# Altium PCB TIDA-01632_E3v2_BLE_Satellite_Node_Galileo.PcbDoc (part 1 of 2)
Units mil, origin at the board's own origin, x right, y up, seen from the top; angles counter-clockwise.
Board outline 3000 x 1875.2 mil, 6 copper layers (Top Layer, Layer2, Layer3, Layer4, Layer5, Bottom Layer), stack 33.151 mil thick; 76 components, 48 nets, 235 pads, 260 vias.
Unrouted connection lines stored in the file: 1.
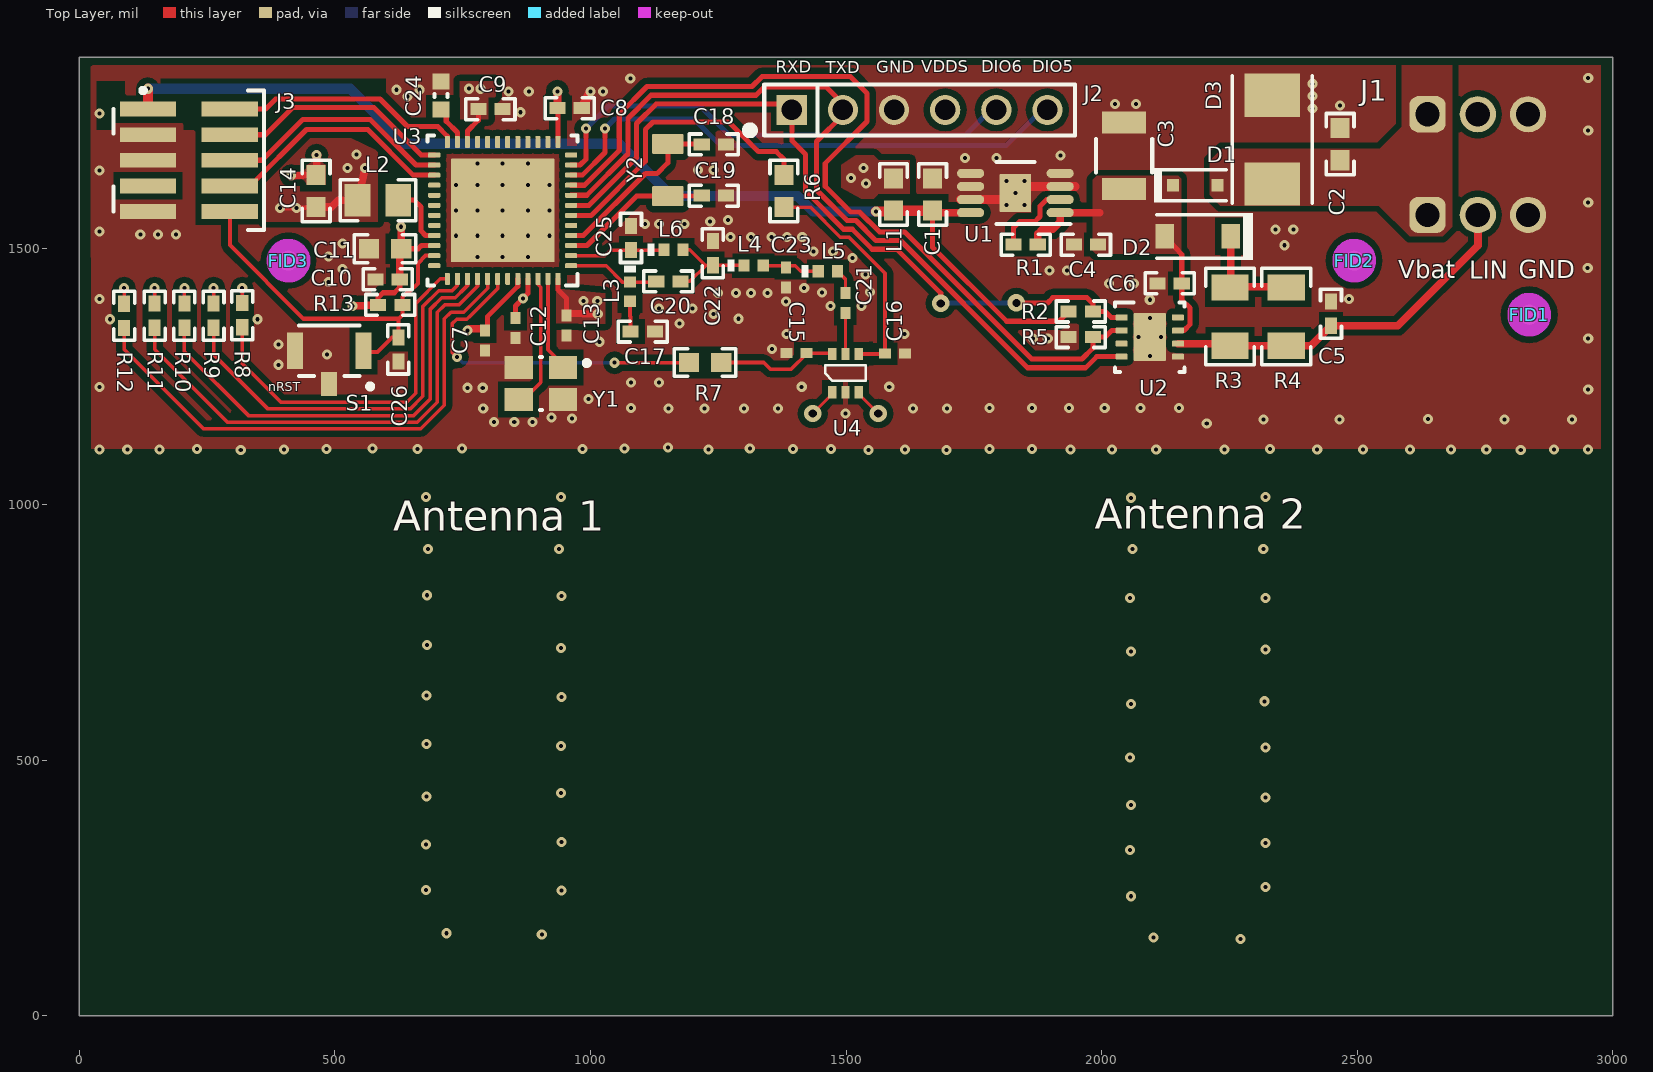
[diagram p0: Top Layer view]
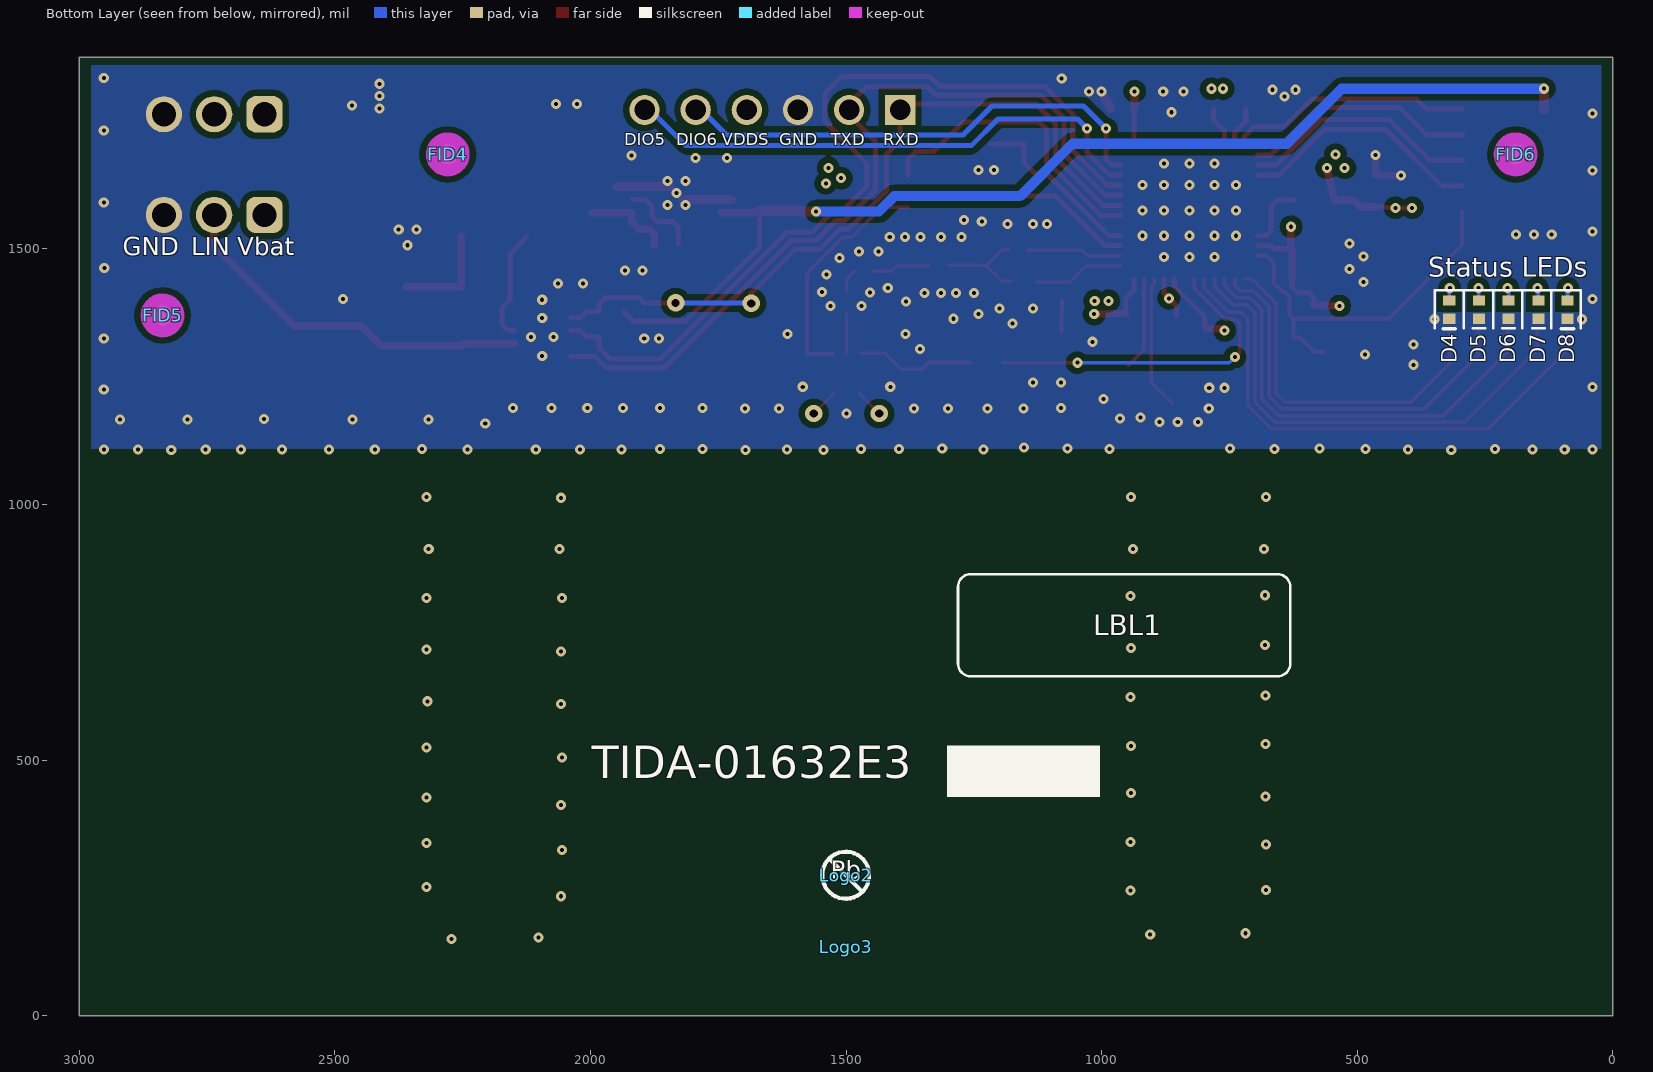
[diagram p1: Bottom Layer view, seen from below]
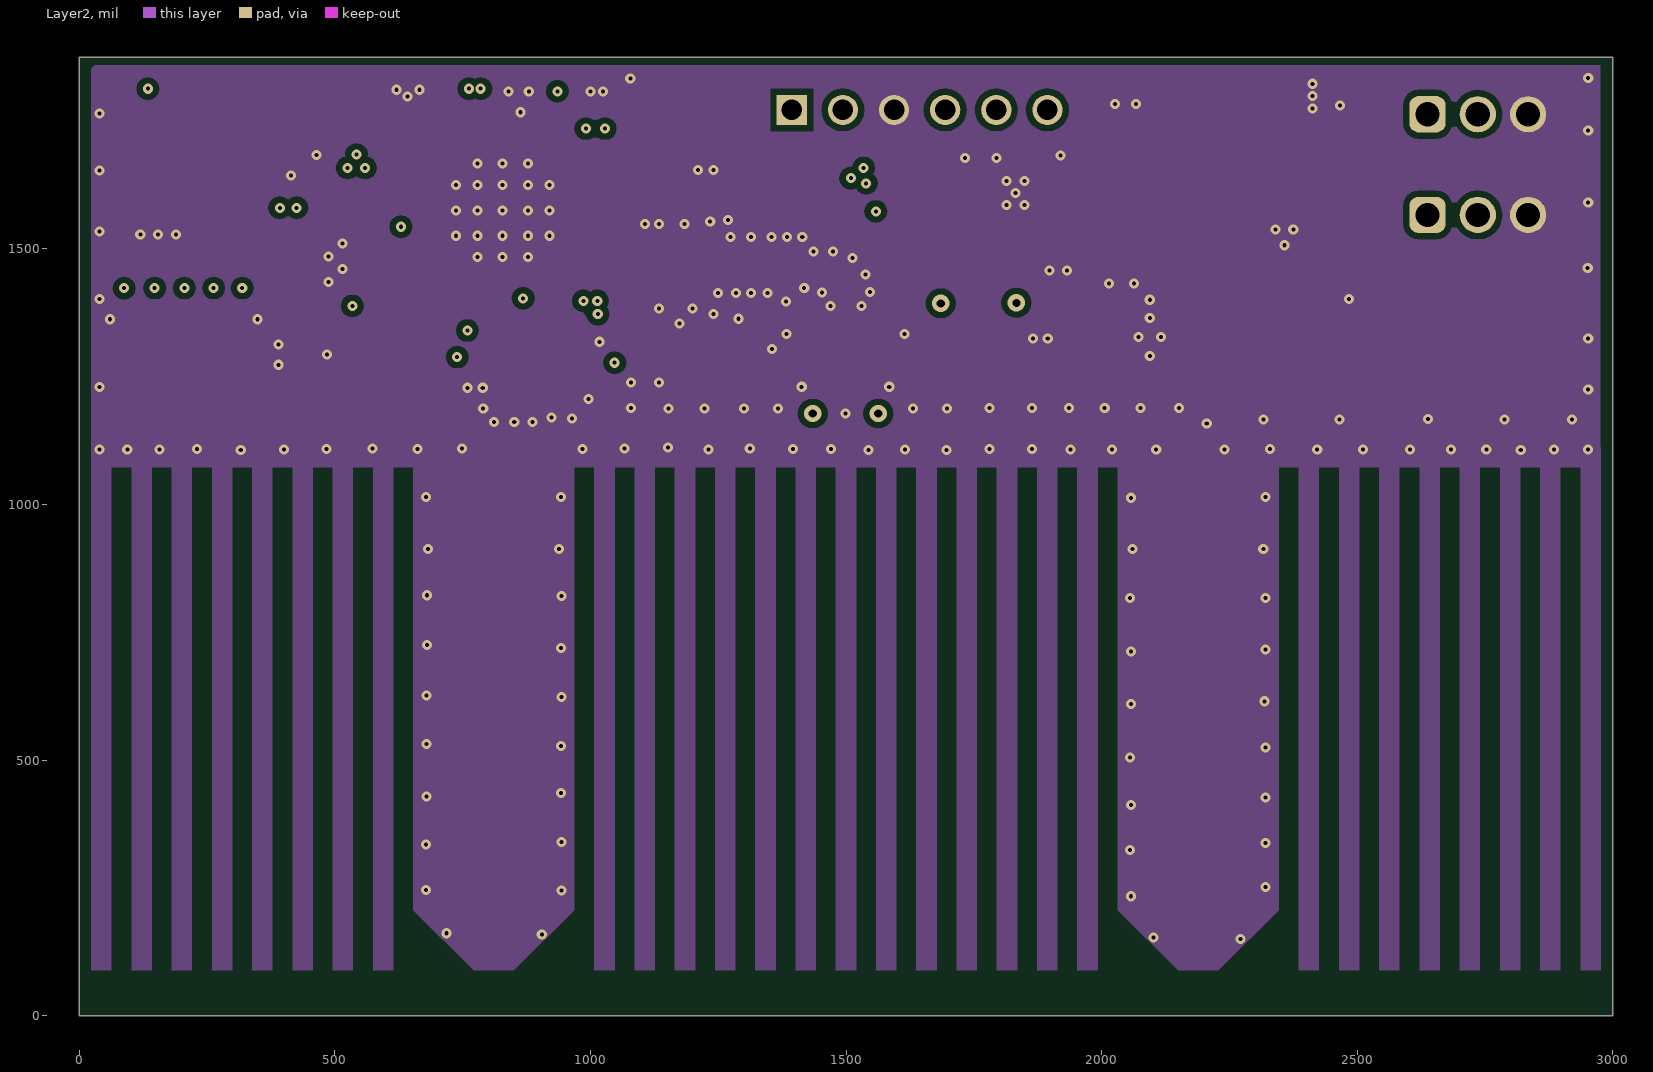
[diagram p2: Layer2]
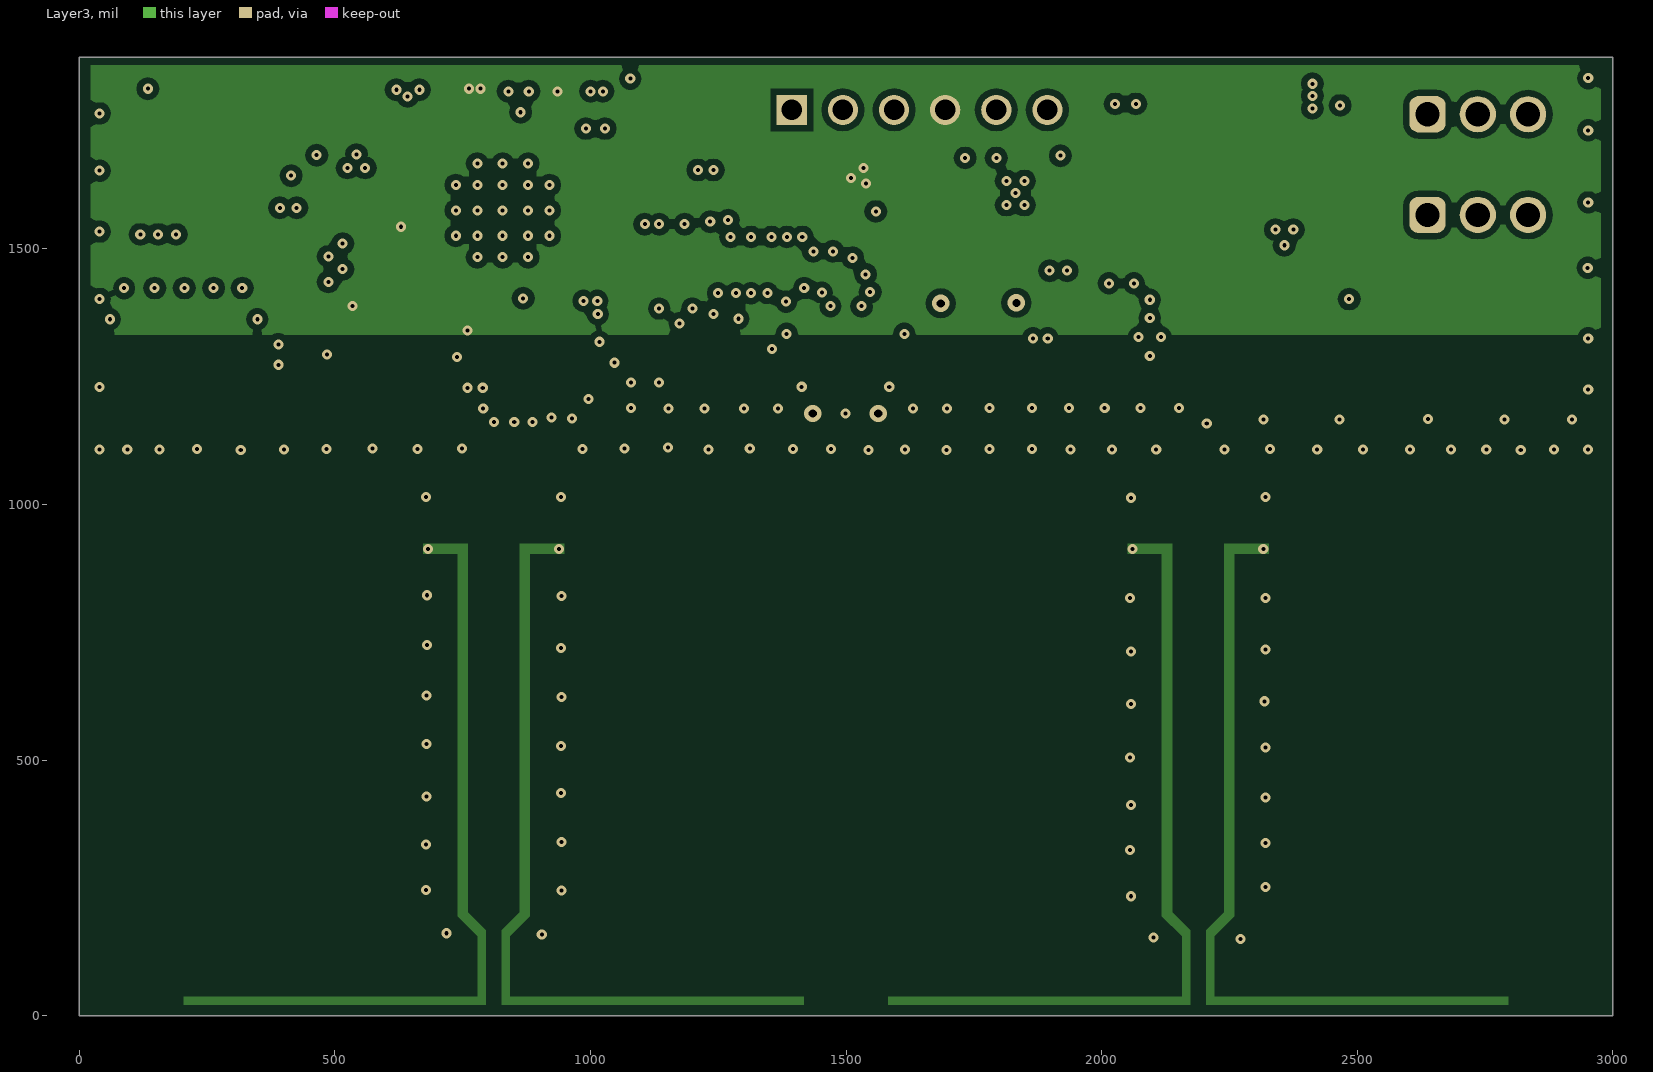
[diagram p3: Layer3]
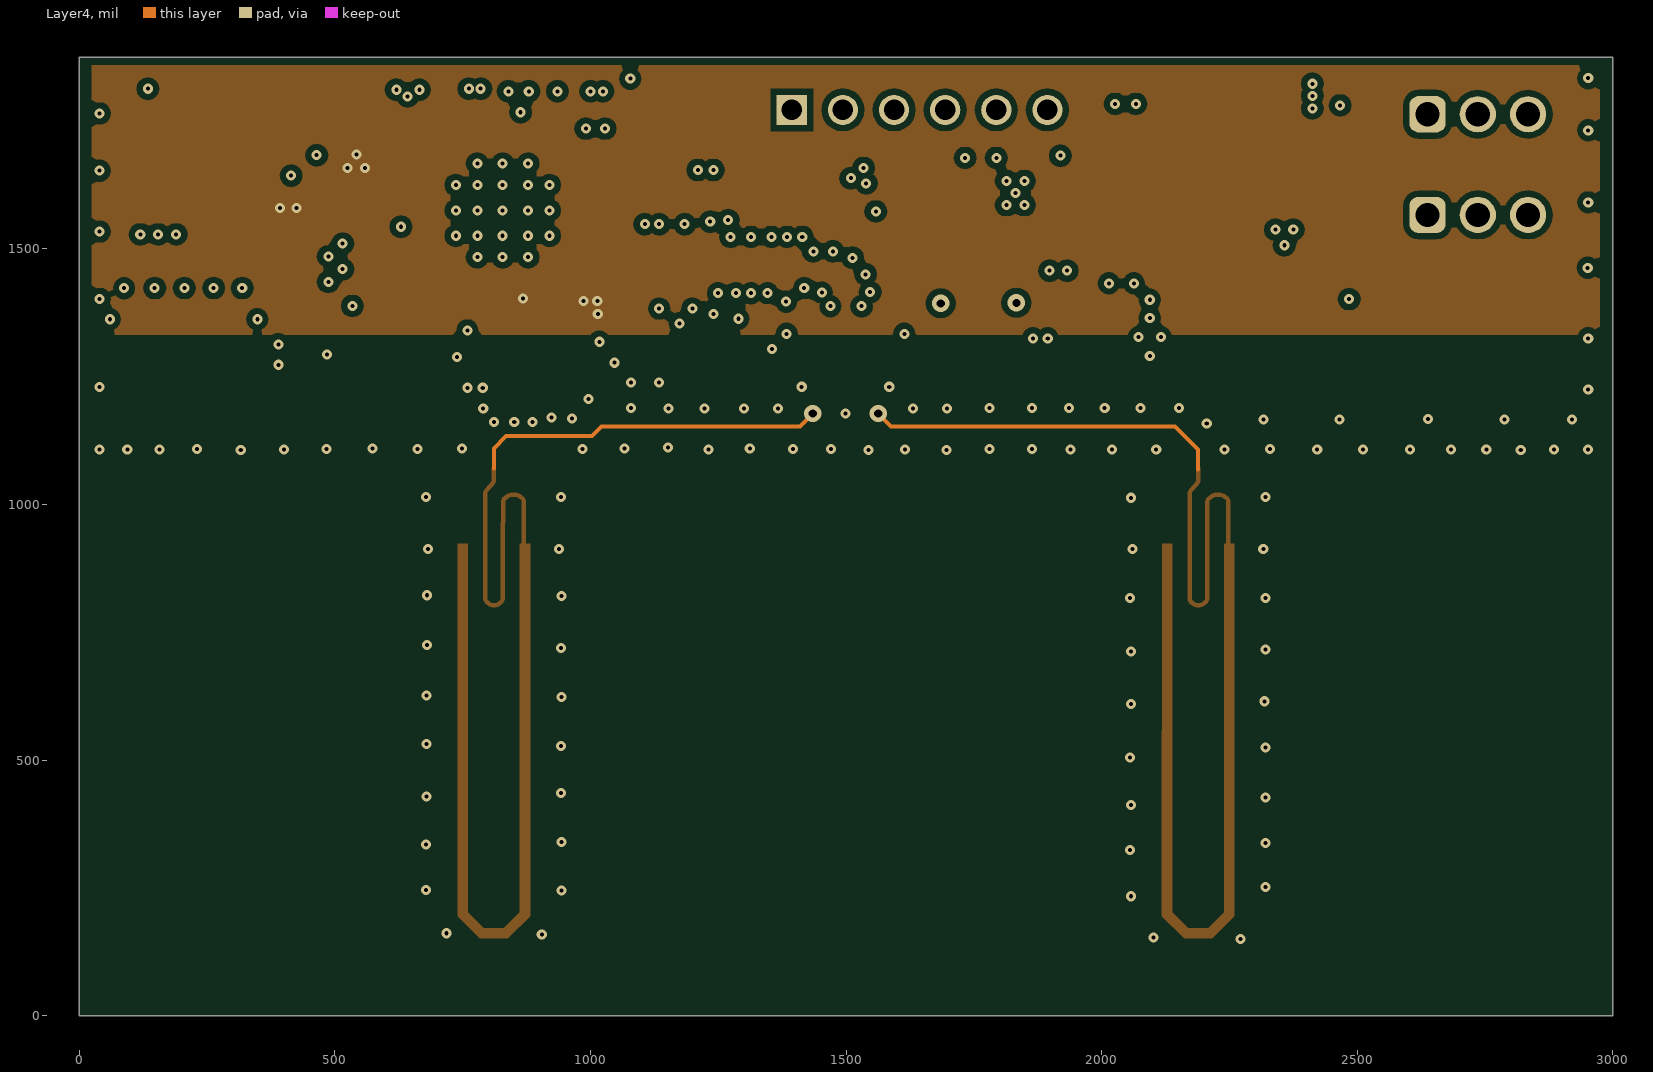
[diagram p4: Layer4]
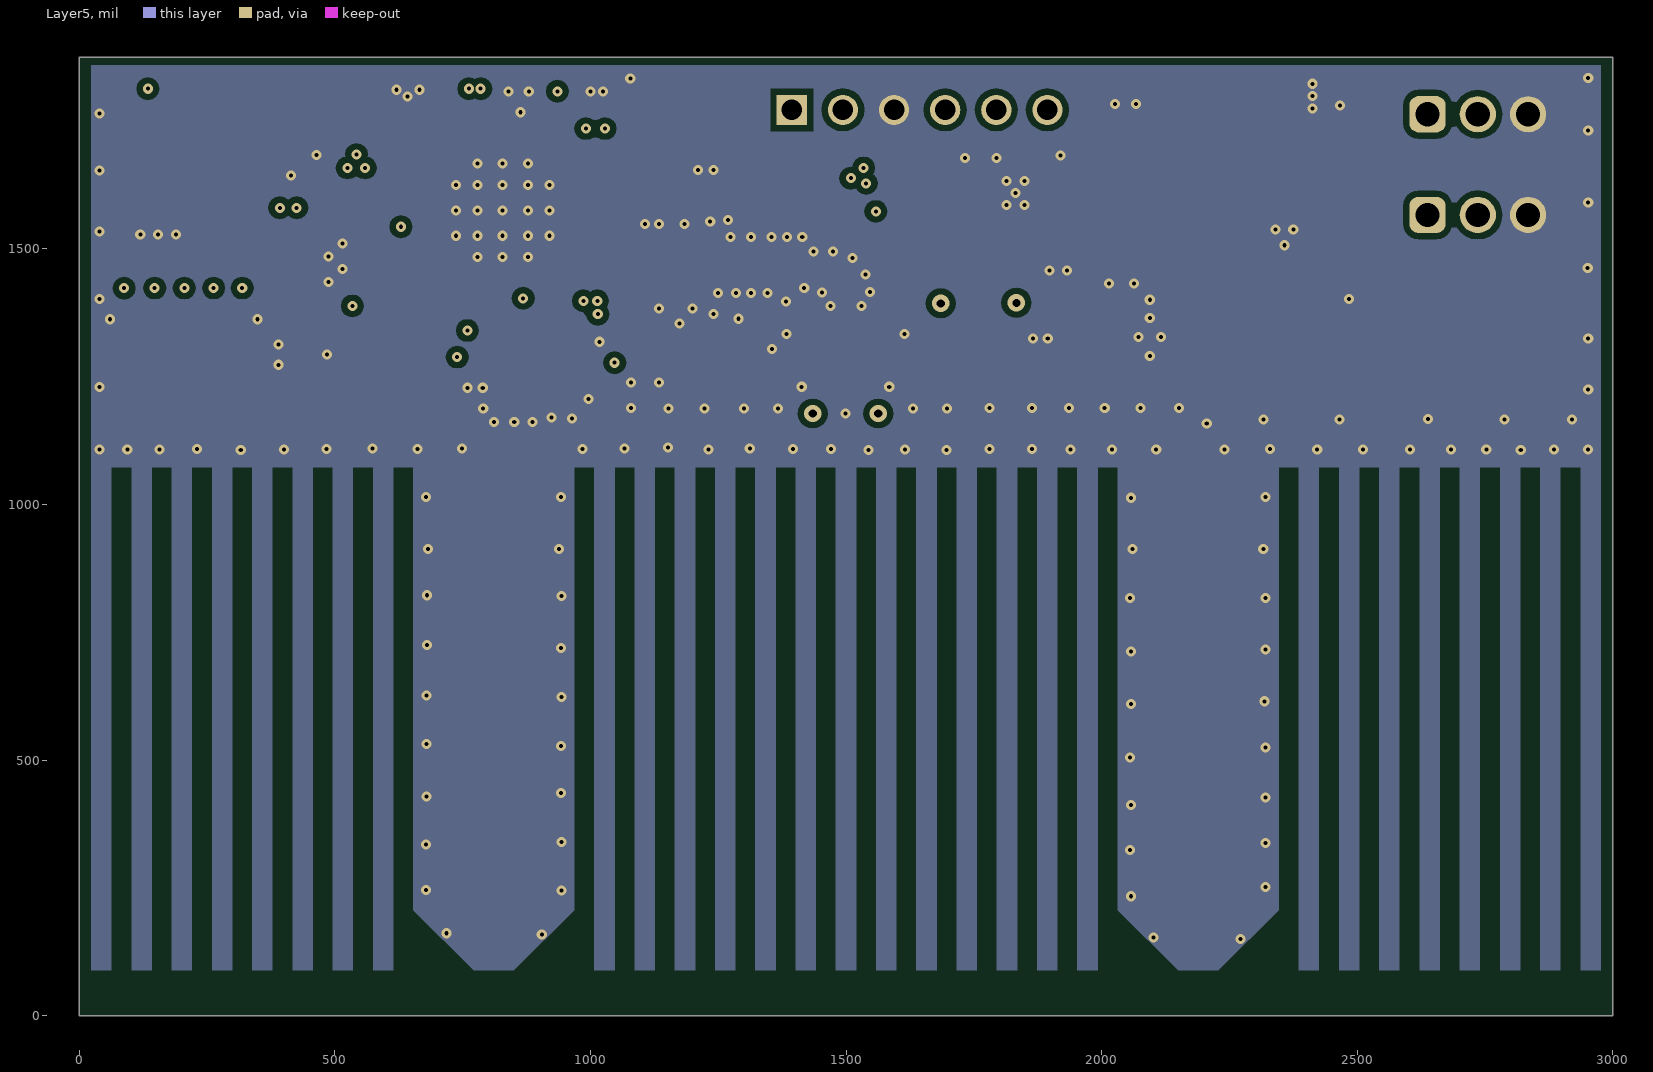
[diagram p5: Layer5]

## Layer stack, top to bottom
Top Solder: solder mask 0.4, Solder Resist, Dk 3.5
Top Layer: signal copper 1.378
Dielectric1: core 3.937, FR-4, Dk 4.1
Layer2: signal copper 0.709
Dielectric2: prepreg 7.874, FR-4, Dk 4.1
Layer3: signal copper 0.709
Dielectric3: core 3.937, FR-4, Dk 4.1
Layer4: signal copper 0.709
Dielectric4: prepreg 7.874, FR-4, Dk 4.1
Layer5: signal copper 0.709
Dielectric5: core 3.937, FR-4, Dk 4.1
Bottom Layer: signal copper 1.378
Bottom Solder: solder mask 0.4, Solder Resist, Dk 3.5

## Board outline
0,-0.2 3000,-0.2 3000,1875 0,1875

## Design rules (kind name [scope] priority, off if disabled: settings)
AcuteAngle [All] p1: minimum=4.50000000000000E+0001 checktracksonly=FALSE
AssemblyTestPointUsage [All] p1: valid=2
BoardOutlineClearance BoardOutlineClearance_MountingHoles [OnCopper and InComponentClass('Mounting Holes')] p1: gap=40 ignorepadtopadclearanceinfootprint=FALSE
BoardOutlineClearance BoardOutlineClearance_Poly [OnCopper and IsPoly] p2: gap=25 ignorepadtopadclearanceinfootprint=FALSE except(15: Poly-OutlineEdge Poly-CutoutEdge Region-OutlineEdge Region-CutoutEdge)
BoardOutlineClearance [OnCopper and Not InComponentClass('Logo') and not InComponentClass('FiducialMark') and not InRegion(1000,500,4000,800) and not InPoly] p3: gap=30 ignorepadtopadclearanceinfootprint=FALSE
Clearance Clearance_1 [InNamedPolygon('LAYER2-GND 8')] p1: gap=10 ignorepadtopadclearanceinfootprint=FALSE except(0: Arc-Hole Track-Hole SMDPad-Hole THPad-Hole Via-Hole Fill-Hole Poly-Hole Region-Hole Text-Hole)
Clearance Clearance_Keepouts [((IsTrack Or IsArc) And Not InPoly) And IsFree and IsKeepOut vs ((IsTrack Or IsArc) And Not InPoly) And IsFree and IsKeepOut] p2: gap=0 ignorepadtopadclearanceinfootprint=FALSE
Clearance Clearance_Poly [InPolygon] p3: gap=12 ignorepadtopadclearanceinfootprint=FALSE
Clearance Clearance_FiducialMark [IsKeepOut and InComponentClass('FiducialMark') vs IsPad and InComponentClass('FiducialMark')] p4: gap=0 ignorepadtopadclearanceinfootprint=FALSE
Clearance [All] p5: gap=6 ignorepadtopadclearanceinfootprint=FALSE except(0: Arc-Hole Track-Hole SMDPad-Hole THPad-Hole Via-Hole Fill-Hole Poly-Hole Region-Hole Text-Hole)
ComponentClearance ComponentClearance_MountingHoles_FiducialMarks [InComponentClass('Mounting Holes') vs InComponentClass('FiducialMark')] p1: gap=50 collisioncheckmode=3 verticalgap=10 showdistances=FALSE
ComponentClearance ComponentClearance_Shunt [InComponentClass('Header') vs InComponentClass('Shunt')] p2: gap=0 collisioncheckmode=3 verticalgap=0 showdistances=FALSE
ComponentClearance ComponentClearance_Logo [InComponentClass('Logo')] p3: gap=50 collisioncheckmode=3 verticalgap=10 showdistances=FALSE
ComponentClearance ComponentClearance_ScrewToNut [(HasFootprint('NY PMS 440 0025 PH')) vs (HasFootprint('Keystone_1902C'))] p4: gap=5 collisioncheckmode=3 verticalgap=10 showdistances=FALSE
ComponentClearance ComponentClearance_MountingHoles [InComponentClass('Mounting Holes')] p5: gap=250 collisioncheckmode=3 verticalgap=100000 showdistances=FALSE
ComponentClearance ComponentClearance_SmallPassives [HasFootprint('0201*') or HasFootprint('0402*') or HasFootprint('0508') or HasFootprint('0603*') or HasFootprint('0612') or HasFootprint('0805*') or HasFootprint('0815*') or HasFootprint('0830*') or HasFootprint('1206*') or HasFootprint('1210*') or HasFootprint('1808*') or HasFootprint('1812*') or HasFootprint('1825*') or HasFootprint('2010*') or HasFootprint('2220*') or HasFootprint('2225*') or HasFootprint('2512*') or HasFootprint('2728*') or HasFootprint('3518*') vs HasFootprint('0201*') or HasFootprint('0402*') or HasFootprint('0508') or HasFootprint('0603*') or HasFootprint('0612') or HasFootprint('0805*') or HasFootprint('0815*') or HasFootprint('0830*') or HasFootprint('1206*') or HasFootprint('1210*') or HasFootprint('1808*') or HasFootprint('1812*') or HasFootprint('1825*') or HasFootprint('2010*') or HasFootprint('2220*') or HasFootprint('2225*') or HasFootprint('2512*') or HasFootprint('2728*') or HasFootprint('3518*')] p6: gap=14.96 collisioncheckmode=3 verticalgap=10 showdistances=FALSE
ComponentClearance ComponentClearance_THtoSMT [IsThruComponent vs IsSMTComponent] p7: gap=40 collisioncheckmode=3 verticalgap=30 showdistances=FALSE
ComponentClearance ComponentClearance_THtoTH [IsThruComponent vs IsThruComponent] p8: gap=30 collisioncheckmode=3 verticalgap=30 showdistances=FALSE
ComponentClearance [All] p9: gap=30 collisioncheckmode=3 verticalgap=10 showdistances=FALSE
DiffPairsRouting [All] p1: maxlimit=100 minlimit=10 mostfreqgap=10 toplayer_minwidth=15 toplayer_maxwidth=15 toplayer_prefwidth=15 midlayer1_minwidth=15 midlayer1_maxwidth=15 midlayer1_prefwidth=15 midlayer2_minwidth=15 midlayer2_maxwidth=15 midlayer2_prefwidth=15 midlayer3_minwidth=15 midlayer3_maxwidth=15 midlayer3_prefwidth=15 midlayer4_minwidth=15 midlayer4_maxwidth=15 midlayer4_prefwidth=15 bottomlayer_minwidth=15 bottomlayer_maxwidth=15 bottomlayer_prefwidth=15 maxuncoupledlength=1000
FabricationTestPointUsage TestPointUsage [All] p1: valid=2 allowmultiple=FALSE
FabricationTestpoint Testpoint [All] p1: side=3 testpointundercomponent=TRUE minsize=40 maxsize=100 preferedsize=60 minholesize=0 maxholesize=40 preferedholesize=32 testpointgrid=1 allowsidetop=TRUE allowsidebottom=TRUE usegrid=TRUE gridtolerance=0.01
FanoutControl Fanout_LCC [IsLCC] p1: bgadir=Out bgaviamode=Centered fanoutstyle=Auto fanoutdirection=Alternating viagrid=1 // Fanout_LCC (Default Rule)
FanoutControl Fanout_BGA [IsBGA] p2: bgadir=Out bgaviamode=Centered fanoutstyle=Auto fanoutdirection=Alternating viagrid=1 // Fanout_BGA (Default Rule)
FanoutControl Fanout_Default [All] p4: bgadir=Out bgaviamode=Centered fanoutstyle=Auto fanoutdirection=Alternating viagrid=1 // Fanout_Default (Default Rule)
FanoutControl Fanout_Small [(CompPinCount < 5)] p5: bgadir=Out bgaviamode=Centered fanoutstyle=Auto fanoutdirection=OutThenIn viagrid=1 // Fanout_Small (Default Rule)
HoleSize [All] p1: absolutevalues=TRUE maxlimit=251 minlimit=7.87 maxpercent=80.000 minpercent=20.000
MinimumAnnularRing MinimumAnnularRing_ThermalPadVias [IsVia and InAnyComponent] p1: minimumring=5.9
MinimumAnnularRing [All] p2: minimumring=5.9
MinimumSolderMaskSliver MinimumSolderMaskSliver_Logo [InComponentClass('Logo') vs InComponentClass('Logo')] p1: minsoldermaskwidth=0.7
MinimumSolderMaskSliver [All] p2: minsoldermaskwidth=2.9
PlaneClearance [All] p1: clearance=15
PlaneConnect [All] p1: planeconnectstyle=Direct reliefexpansion=10 reliefentries=4 reliefconductorwidth=10 reliefairgap=10
PolygonConnect PolygonConnect_54 [All vs IsNamedPolygon('TOP_LAYER_DIO_6_P217')] p1: thpad.connectstyle=Direct thpad.reliefconductorwidth=10 thpad.reliefentries=4 thpad.polygonreliefangle="90 Angle" thpad.airgapwidth=10 smdpad.connectstyle=Direct smdpad.reliefconductorwidth=10 smdpad.reliefentries=4 smdpad.polygonreliefangle="90 Angle" smdpad.airgapwidth=10 via.connectstyle=Relief via.reliefconductorwidth=10 via.reliefentries=4 via.polygonreliefangle="90 Angle" via.airgapwidth=10
PolygonConnect PolygonConnect_53 [All vs IsNamedPolygon('TOP_LAYER_DIO_5_P216')] p2: connectstyle=Direct reliefconductorwidth=10 reliefentries=4 polygonreliefangle="90 Angle" airgapwidth=10
PolygonConnect PolygonConnect_52 [All vs IsNamedPolygon('TOP_LAYER_VDDS_P221')] p3: connectstyle=Direct reliefconductorwidth=10 reliefentries=4 polygonreliefangle="90 Angle" airgapwidth=10
PolygonConnect PolygonConnect_51 [All vs IsNamedPolygon('TOP_LAYER_VDDR_P243')] p4: connectstyle=Direct reliefconductorwidth=10 reliefentries=4 polygonreliefangle="90 Angle" airgapwidth=10
PolygonConnect PolygonConnect_50 [All vs IsNamedPolygon('TOP_LAYER_VDDR_P218')] p5: connectstyle=Direct reliefconductorwidth=10 reliefentries=4 polygonreliefangle="90 Angle" airgapwidth=10
PolygonConnect PolygonConnect_49 [All vs IsNamedPolygon('TOP_LAYER_GND_P247')] p6: connectstyle=Direct reliefconductorwidth=10 reliefentries=4 polygonreliefangle="90 Angle" airgapwidth=10
PolygonConnect PolygonConnect_48 [All vs IsNamedPolygon('TOP_LAYER_DIO_5_P247')] p7: connectstyle=Direct reliefconductorwidth=10 reliefentries=4 polygonreliefangle="90 Angle" airgapwidth=10
PolygonConnect PolygonConnect_47 [All vs IsNamedPolygon('TOP_LAYER_DIO_6_P245')] p8: connectstyle=Direct reliefconductorwidth=10 reliefentries=4 polygonreliefangle="90 Angle" airgapwidth=10
PolygonConnect PolygonConnect_46 [All vs IsNamedPolygon('TOP_LAYER_DIO_6_P245')] p9: connectstyle=Direct reliefconductorwidth=10 reliefentries=4 polygonreliefangle="90 Angle" airgapwidth=10
PolygonConnect PolygonConnect_45 [All vs IsNamedPolygon('TOP_LAYER_VDDR_P240')] p10: connectstyle=Direct reliefconductorwidth=10 reliefentries=4 polygonreliefangle="90 Angle" airgapwidth=10
PolygonConnect PolygonConnect_44 [All vs IsNamedPolygon('TOP_LAYER_VDDR_P240')] p11: connectstyle=Direct reliefconductorwidth=10 reliefentries=4 polygonreliefangle="90 Angle" airgapwidth=10
PolygonConnect PolygonConnect_43 [All vs IsNamedPolygon('TOP_LAYER_VBATT_P217')] p12: connectstyle=Direct reliefconductorwidth=10 reliefentries=4 polygonreliefangle="90 Angle" airgapwidth=10
PolygonConnect PolygonConnect_42 [All vs IsNamedPolygon('TOP_LAYER_VSUP_P218')] p13: connectstyle=Direct reliefconductorwidth=10 reliefentries=4 polygonreliefangle="90 Angle" airgapwidth=10
PolygonConnect PolygonConnect_41 [All vs IsNamedPolygon('TOP_LAYER_VDDS_P219')] p14: connectstyle=Direct reliefconductorwidth=10 reliefentries=4 polygonreliefangle="90 Angle" airgapwidth=10
PolygonConnect PolygonConnect_40 [All vs IsNamedPolygon('LAYER2_GND_P240')] p15: connectstyle=Direct reliefconductorwidth=10 reliefentries=4 polygonreliefangle="90 Angle" airgapwidth=10
PolygonConnect PolygonConnect_39 [All vs IsNamedPolygon('LAYER5_GND_P241')] p16: connectstyle=Direct reliefconductorwidth=10 reliefentries=4 polygonreliefangle="90 Angle" airgapwidth=10
PolygonConnect PolygonConnect_38 [All vs IsNamedPolygon('BOTTOM_LAYER_GND_P243')] p17: connectstyle=Direct reliefconductorwidth=10 reliefentries=4 polygonreliefangle="90 Angle" airgapwidth=10
PolygonConnect PolygonConnect_37 [All vs IsNamedPolygon('LAYER3_VDDS_P245')] p18: connectstyle=Direct reliefconductorwidth=10 reliefentries=4 polygonreliefangle="90 Angle" airgapwidth=10
PolygonConnect PolygonConnect_36 [All vs IsNamedPolygon('LAYER4_VDDR_P249')] p19: connectstyle=Direct reliefconductorwidth=10 reliefentries=4 polygonreliefangle="90 Angle" airgapwidth=10
PolygonConnect PolygonConnect_35 [All vs IsNamedPolygon('LAYER3_GND_P242')] p20: connectstyle=Direct reliefconductorwidth=10 reliefentries=4 polygonreliefangle="90 Angle" airgapwidth=10
PolygonConnect PolygonConnect_34 [All vs IsNamedPolygon('TOP_LAYER_GND_P243')] p21: connectstyle=Direct reliefconductorwidth=10 reliefentries=4 polygonreliefangle="90 Angle" airgapwidth=10
PolygonConnect PolygonConnect_33 [All vs IsNamedPolygon('LAYER4_GND_P244')] p22: connectstyle=Direct reliefconductorwidth=10 reliefentries=4 polygonreliefangle="90 Angle" airgapwidth=10
PolygonConnect PolygonConnect_32 [All vs IsNamedPolygon('TOP_LAYER_VDDR_P216')] p23: connectstyle=Direct reliefconductorwidth=10 reliefentries=4 polygonreliefangle="90 Angle" airgapwidth=10
PolygonConnect PolygonConnect_31 [All vs IsNamedPolygon('TOP_LAYER_GND_P214')] p24: connectstyle=Direct reliefconductorwidth=10 reliefentries=4 polygonreliefangle="90 Angle" airgapwidth=10
PolygonConnect PolygonConnect_30 [All vs IsNamedPolygon('TOP_LAYER_VDDR_P214')] p25: connectstyle=Direct reliefconductorwidth=10 reliefentries=4 polygonreliefangle="90 Angle" airgapwidth=10
PolygonConnect PolygonConnect_29 [All vs IsNamedPolygon('TOP_LAYER_VDDR_P208')] p26: connectstyle=Direct reliefconductorwidth=10 reliefentries=4 polygonreliefangle="90 Angle" airgapwidth=10
PolygonConnect PolygonConnect_28 [All vs IsNamedPolygon('TOP_LAYER_GND_P202')] p27: connectstyle=Direct reliefconductorwidth=10 reliefentries=4 polygonreliefangle="90 Angle" airgapwidth=10
PolygonConnect PolygonConnect_27 [All vs IsNamedPolygon('TOP_LAYER_VDDS_P142')] p28: connectstyle=Direct reliefconductorwidth=10 reliefentries=4 polygonreliefangle="90 Angle" airgapwidth=10
PolygonConnect PolygonConnect_26 [All vs IsNamedPolygon('TOP_LAYER_VSUP_P140')] p29: connectstyle=Direct reliefconductorwidth=10 reliefentries=4 polygonreliefangle="90 Angle" airgapwidth=10
PolygonConnect PolygonConnect_25 [All vs IsNamedPolygon('TOP_LAYER_VBATT_P138')] p30: connectstyle=Direct reliefconductorwidth=10 reliefentries=4 polygonreliefangle="90 Angle" airgapwidth=10
PolygonConnect PolygonConnect_24 [All vs IsNamedPolygon('TOP_LAYER_VDDS_P140')] p31: connectstyle=Direct reliefconductorwidth=10 reliefentries=4 polygonreliefangle="90 Angle" airgapwidth=10
PolygonConnect PolygonConnect_23 [All vs IsNamedPolygon('TOP_LAYER_GND_P200')] p32: connectstyle=Direct reliefconductorwidth=10 reliefentries=4 polygonreliefangle="90 Angle" airgapwidth=10
PolygonConnect PolygonConnect_22 [All vs IsNamedPolygon('TOP_LAYER_VSUP_P138')] p33: connectstyle=Direct reliefconductorwidth=10 reliefentries=4 polygonreliefangle="90 Angle" airgapwidth=10
PolygonConnect PolygonConnect_21 [All vs IsNamedPolygon('TOP_LAYER_GND_P198')] p34: connectstyle=Direct reliefconductorwidth=10 reliefentries=4 polygonreliefangle="90 Angle" airgapwidth=10
PolygonConnect PolygonConnect_20 [All vs IsNamedPolygon('TOP_LAYER_VDDS_P138')] p35: connectstyle=Direct reliefconductorwidth=10 reliefentries=4 polygonreliefangle="90 Angle" airgapwidth=10
PolygonConnect PolygonConnect_19 [All vs IsNamedPolygon('TOP_LAYER_VDDS_P202')] p36: connectstyle=Direct reliefconductorwidth=10 reliefentries=4 polygonreliefangle="90 Angle" airgapwidth=10
PolygonConnect PolygonConnect_18 [All vs IsNamedPolygon('LAYER4_VDDR_P208')] p37: connectstyle=Direct reliefconductorwidth=10 reliefentries=4 polygonreliefangle="90 Angle" airgapwidth=10
PolygonConnect PolygonConnect_17 [All vs IsNamedPolygon('LAYER3_VDDS_P206')] p38: connectstyle=Direct reliefconductorwidth=10 reliefentries=4 polygonreliefangle="90 Angle" airgapwidth=10
PolygonConnect PolygonConnect_16 [All vs IsNamedPolygon('TOP_LAYER_GND_P196')] p39: connectstyle=Direct reliefconductorwidth=10 reliefentries=4 polygonreliefangle="90 Angle" airgapwidth=10
PolygonConnect PolygonConnect_15 [All vs IsNamedPolygon('TOP_LAYER_GND_P196')] p40: connectstyle=Direct reliefconductorwidth=10 reliefentries=4 polygonreliefangle="90 Angle" airgapwidth=10
PolygonConnect PolygonConnect_14 [All vs IsNamedPolygon('BOTTOM_LAYER_GND_P202')] p41: connectstyle=Direct reliefconductorwidth=10 reliefentries=4 polygonreliefangle="90 Angle" airgapwidth=10
PolygonConnect PolygonConnect_13 [All vs IsNamedPolygon('LAYER5_GND_P200')] p42: connectstyle=Direct reliefconductorwidth=10 reliefentries=4 polygonreliefangle="90 Angle" airgapwidth=10
PolygonConnect PolygonConnect_12 [All vs IsNamedPolygon('LAYER2_GND_P198')] p43: connectstyle=Direct reliefconductorwidth=10 reliefentries=4 polygonreliefangle="90 Angle" airgapwidth=10
PolygonConnect PolygonConnect_11 [All vs IsNamedPolygon('LAYER2_GND_P198')] p44: connectstyle=Direct reliefconductorwidth=10 reliefentries=4 polygonreliefangle="90 Angle" airgapwidth=10
PolygonConnect PolygonConnect_10 [All vs IsNamedPolygon('LAYER2-GND 8')] p45: connectstyle=Direct reliefconductorwidth=10 reliefentries=4 polygonreliefangle="90 Angle" airgapwidth=10
PolygonConnect PolygonConnect_9 [All vs IsNamedPolygon('LAYER2-GND 8')] p46: connectstyle=Direct reliefconductorwidth=10 reliefentries=4 polygonreliefangle="90 Angle" airgapwidth=10
PolygonConnect PolygonConnect_8 [All vs IsNamedPolygon('LAYER5_GND_P200')] p47: thpad.connectstyle=Direct thpad.reliefconductorwidth=10 thpad.reliefentries=4 thpad.polygonreliefangle="90 Angle" thpad.airgapwidth=10 smdpad.connectstyle=NoConnect smdpad.reliefconductorwidth=10 smdpad.reliefentries=4 smdpad.polygonreliefangle="90 Angle" smdpad.airgapwidth=10 via.connectstyle=Direct via.reliefconductorwidth=10 via.reliefentries=4 via.polygonreliefangle="90 Angle" via.airgapwidth=10
PolygonConnect PolygonConnect_7 [All vs IsNamedPolygon('LAYER2_GND_P198')] p48: connectstyle=Direct reliefconductorwidth=10 reliefentries=4 polygonreliefangle="90 Angle" airgapwidth=10
PolygonConnect PolygonConnect_6 [All vs IsNamedPolygon('LAYER2-GND 8')] p49: connectstyle=Direct reliefconductorwidth=10 reliefentries=4 polygonreliefangle="90 Angle" airgapwidth=10
PolygonConnect PolygonConnect_5 [All vs IsNamedPolygon('LAYER5-GND 5') Or  IsNamedPolygon('LAYER5-GND 3') Or  IsNamedPolygon('LAYER5-GND 6') Or  IsNamedPolygon('LAYER5-GND 4') Or  IsNamedPolygon('LAYER5-GND 7') Or  IsNamedPolygon('LAYER5-GND 2')] p50: connectstyle=Direct reliefconductorwidth=10 reliefentries=4 polygonreliefangle="90 Angle" airgapwidth=10
PolygonConnect PolygonConnect_4 [All vs IsNamedPolygon('LAYER2-GND 8') Or  IsNamedPolygon('LAYER2-GND 6') Or  IsNamedPolygon('LAYER2-GND 8') Or  IsNamedPolygon('LAYER2-GND 7')] p51: connectstyle=Direct reliefconductorwidth=10 reliefentries=4 polygonreliefangle="90 Angle" airgapwidth=10
PolygonConnect PolygonConnect_3 [All vs IsNamedPolygon('LAYER3-GND 2') Or  IsNamedPolygon('LAYER3-GND 4') Or  IsNamedPolygon('LAYER3-GND 3')] p52: connectstyle=Direct reliefconductorwidth=10 reliefentries=4 polygonreliefangle="90 Angle" airgapwidth=10
PolygonConnect PolygonConnect_2 [All vs IsNamedPolygon('LAYER3-GND 5')] p53: connectstyle=Direct reliefconductorwidth=10 reliefentries=4 polygonreliefangle="90 Angle" airgapwidth=10
PolygonConnect PolygonConnect_1 [All vs IsNamedPolygon('LAYER2-GND 9') Or  IsNamedPolygon('LAYER5-GND 7')] p54: connectstyle=Direct reliefconductorwidth=10 reliefentries=4 polygonreliefangle="90 Angle" airgapwidth=10
PolygonConnect [All] p55: connectstyle=Direct reliefconductorwidth=10 reliefentries=4 polygonreliefangle="90 Angle" airgapwidth=10
RoutingVias ThermalPadVias [IsVia and InAnyComponent] p1: holewidth=7.87 width=19.68 viastyle="Through Hole" minholewidth=7.87 minwidth=19.68 maxholewidth=12.99 maxwidth=23.62
RoutingVias [All] p2: holewidth=16 width=34 viastyle="Through Hole" minholewidth=7.87 minwidth=19 maxholewidth=40 maxwidth=65
SilkToBoardRegionClearance [Not ((IsComment or IsDesignator) And (Hide <> 'False')) and not InRegion(1000,500,4000,800)] p1:
SilkToSilkClearance SilkToSilkClearance_Pb-FreeLogo [(HasFootprint('Pb-Free_Overlay_Medium') OR HasFootprint('Pb-Free_Overlay_Small')) vs (HasFootprint('Pb-Free_Overlay_Medium') OR HasFootprint('Pb-Free_Overlay_Small'))] p1: silktosilkclearance=0
SilkToSilkClearance [All] p2: silktosilkclearance=4
SilkToSolderMaskClearance SilkToComponentPadClearance [(IsPad or IsFill or IsRegion) and InAnycomponent] p1: minsilkscreentomaskgap=5 clearancetoexposedcopper=TRUE
SilkToSolderMaskClearance "Silk to Solder Mask Opening" [All] p2: minsilkscreentomaskgap=4 clearancetoexposedcopper=FALSE
SolderMaskExpansion [All] p1: expansion=1.97
UnRoutedNet [All] p1: checkbadconnections=TRUE
Width [All] p1: maxlimit=100 minlimit=5 preferedwidth=10 minimp=50.000000 maximp=50.000000 favimp=50.000000 checkconnectedcopper=TRUE
13 further rules are at their usual default settings.

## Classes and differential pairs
component class TIDA-01632_E3v2_BLE_Satellite_Node_Main_Galileo: C1 C2 C3 C4 C5 C6 C7 C8 C9 C10 C11 C12 C13 C14 C15 C16 C17 C18 C19 C20 C21 C22 C23 C24 C25 C? D1 D2 D3 D4 D5 D6 D7 D8 D? J1 J2 J3 J? L1 L2 L3 L4 L5 L6 R1 R2 R3 R4 R5 R6 R7 R8 R9 R10 R11 R12 R13 R? S1 U1 U2 U3 U4 U? Y1 Y2
component class TIDA-01632_E3v2_BLE_Satellite_Node_Hardware_Galileo: FID1 FID2 FID3 FID4 FID5 FID6 LBL1 Logo2 Logo3 ZZ1 ZZ2 ZZ3 ZZ4
component class FiducialMark: FID1 FID2 FID3 FID4 FID5 FID6
component class AssemblyNote: ZZ1 ZZ2 ZZ3 ZZ4
component class Label: LBL1
component class Header: J2

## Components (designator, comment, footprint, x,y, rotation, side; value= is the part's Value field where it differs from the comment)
C1 "GCM188R70J225KE22D" 0603 1669.41,1606.38 r90 top value=2.2uF
C2 "06035C104KAZ2A" 0603 2466.52,1704.96 r90 top value=0.1uF
C3 "UMK325AB7106KMHT" 1210_280 2044,1682 r270 top value=10uF
C4 "GCM155R71H104KE02D" 0402 1969.41,1508.51 r180 top value=0.1uF
C5 "GRM155R72A221KA01D" 0402 2448.8,1373.27 r90 top value=220pF
C6 "GCM155R71H104KE02D" 0402 2133.27,1432.59 r180 top value=0.1uF
C7 "CL05B104KP5NNNC" 0402L 794,1321 r270 top value=0.1uF
C8 "CL05B104KP5NNNC" 0402 959.41,1775.38 r0 top value=0.1uF
C9 "CL05B104KP5NNNC" 0402 804.41,1773.38 r0 top value=0.1uF
C10 "CL05B104KP5NNNC" 0402 603.41,1440.38 r180 top value=0.1uF
C11 "GRM188Z71A106MA73D" 0603 598.41,1500.38 r180 top value=10uF
C12 "CL05B104KP5NNNC" 0402L 853.41,1345.38 r270 top value=0.1uF
C13 "CL05B104KP5NNNC" 0402L 953.41,1350.38 r270 top value=0.1uF
C14 "GRM188Z71A106MA73D" 0603 463.41,1613.38 r90 top value=10uF
C15 "GRM1555C1H120JA01D" 0402L 1403,1296 r180 top value=12pF
C16 "GRM1555C1H120JA01D" 0402L 1596,1295 r0 top value=12pF
C17 "GRM1555C1H6R8CA01D" 0402 1102.41,1338.38 r0 top value=6.8pF
C18 "GRM1555C1H120JA01D" 0402 1241.41,1704.38 r0 top value=12pF
C19 "GRM1555C1H120JA01D" 0402 1241.41,1604.38 r0 top value=12pF
C20 "GRM1555C1H1R0CA01D" 0402 1152.41,1436.38 r180 top value=1pF
C21 "GRM1555C1H120JA01D" 0402L 1499,1393.94 r90 top value=12pF
C22 "GRM1555C1H1R0CA01D" 0402 1239.41,1491.62 r90 top value=1pF
C23 "GRM1555C1H1R0CA01D" 0402L 1382.41,1444.38 r270 top value=1pF
C24 "GRM188R71A105KA61D" 0603L 707.68,1799.94 r90 top value=1uF
C25 "GRM1555C1H1R0CA01D" 0402 1079.41,1521.38 r90 top value=1pF
C26 "CL05B104KP5NNNC" 0402 624.41,1303.38 r270 top value=0.1uF
D1 "BAS20HT1G" SOD-323 2183.27,1624.56 r0 top value=200V
D2 "1N4148W-TP" SOD-123 2188.27,1524.56 r180 top value=100V
D3 "SM6T39CA" SMB-Bi 2334,1714 r270 top value=39V
D4 "SML-P12PTT86" SML-P1_GREEN 319.87,1381.14 r90 bottom value=Green
D5 "SMLP12BC7TT86" LED_SMLP12_BLUE 261.8,1381.14 r270 bottom value=Blue
D6 "SML-P12YTT86" LED_SMLP12_YELLOW 203.72,1381.14 r270 bottom value=Yellow
D7 "SML-P12DTT86" LED_SMLP12_ORANGE 145.65,1381.14 r270 bottom value=Orange
D8 "SML-P12VTT86" SML-P1_RED 88.57,1381.14 r90 bottom value=Red
FID1 "Fiducial" Fiducial10-20#1 2836.6,1371.3 r0 top
FID2 "Fiducial" Fiducial10-20#1 2494.08,1477 r0 top
FID3 "Fiducial" Fiducial10-20#2 409.41,1477.01 r0 top
FID4 "Fiducial" Fiducial10-20#1 2279,1685 r90 bottom
FID5 "Fiducial" Fiducial10-20#1 2837,1370 r90 bottom
FID6 "Fiducial" Fiducial10-20#1 190,1685 r90 bottom
J1 "1770898" Phoenix_1770898 2736,1665 r0 top
J2 "PEC06SAAN" Sullins_PEC06SAAN 1644,1772 r0 top
J3 "FTSH-105-01-F-DV-K" Samtec_FTSH-105-01-x-DV-K 214.41,1673.38 r0 top
L1 "BLM18HE152SN1D" 0603 1592.91,1606.38 r270 top value="1500 ohm"
L2 "CKS2125100M-T" 0805_HV 584.41,1595.38 r180 top value=10uH
L3 "LQG15HS2N4S02D" IND_LQG15H 1077.41,1416.38 r270 top value=2.4nH
L4 "LQG15HS2N0S02D" IND_LQG15H 1319.41,1467.38 r0 top value=2nH
L5 "LQG15HS2N0S02D" IND_LQG15H 1464.41,1456.38 r0 top value=2nH
L6 "LQG15HS2N4S02D" IND_LQG15H 1162.41,1498.38 r0 top value=2.4nH
LBL1 "THT-14-423-10" Label_650x200 955.94,763.85 r180 bottom
Logo2 "Pb-Free Symbol" Pb-Free_Overlay_Small 1500.51,274.8 r180 bottom
Logo3 "FCC disclaimer" FCC_disclaimer 1500.51,134.8 r180 bottom
R1 "CRCW04020000Z0ED" 0402 1851.44,1508.51 r180 top value=0
R2 "CRCW040210K0JNED" 0402 1959.27,1377.59 r180 top value=10k
R3 "RC1206FR-072KL" 1206 2251.27,1367.59 r90 top value=2.00k
R4 "RC1206FR-072KL" 1206 2361.27,1367.59 r90 top value=2.00k
R5 "ERJ-2GEJ104X" 0402 1959.27,1327.59 r0 top value=100k
R6 "CRCW06031K00JNEA" 0603 1378.58,1613.38 r270 top value=1.0k
R7 "CRCW06031K00JNEA" 0603 1224.39,1277.8 r0 top value=1.0k
R8 "CRCW0402220RJNED" 0402 318.88,1370.32 r270 top value=220
R9 "CRCW0402130RJNED" 0402 262.78,1369.33 r270 top value=130
R10 "CRCW0402470RJNED" 0402 205.69,1369.33 r270 top value=470
R11 "CRCW0402470RJNED" 0402 147.62,1369.33 r270 top value=470
R12 "CRCW0402430RJNED" 0402 87.81,1369.08 r270 top value=430
R13 "ERJ-2GEJ104X" 0402 608.41,1390.38 r180 top value=100k
S1 "B3U-1100P" SW_B3U-1100P 489,1301 r180 top
U1 "TPS7B8233QDGNRQ1" DGN0008D_N 1831.41,1609.38 r180 top
U2 "TLIN1029DRBRQ1" DRB0008F 2094.27,1327.59 r0 top
U3 "CC2640R2FTWRGZRQ1" RGZ0048N 828.41,1575.38 r180 top
U4 "SKYA21001" SOT-363 1499,1257 r90 top
Y1 "TSX-3225 24.0000MF20G-AC3" EPSON_TSX-3225 902.99,1236.72 r270 top
Y2 "ST3215SB32768C0HSZA1" Kyocera_ST3215SB 1151.41,1654.38 r270 top
ZZ1 "This Assembly Note is for PCB labels only" AssemblyNoteLabel 185,3938 r0 top
ZZ2 "These assemblies are ESD sensitive, ESD precautions shall be observed." AssemblyNote 185,3829.11 r0 top
ZZ3 "These assemblies must be clean and free from flux and all contaminants. Use of no clean flux is not acceptable." AssemblyNote 185,3740.56 r0 top
ZZ4 "These assemblies must comply with workmanship standards IPC-A-610 Class 2, unless otherwise specified." AssemblyNote 185,3652 r0 top

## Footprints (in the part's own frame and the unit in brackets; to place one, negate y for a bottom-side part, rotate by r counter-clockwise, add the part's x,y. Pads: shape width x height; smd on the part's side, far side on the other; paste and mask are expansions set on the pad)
0402 [mm] "0402 from SM-752 data"
  rect 0.8x0.6 smd: 1(-0.6,0) 2(0.6,0)
  silkscreen extent -1.22,-0.52 1.22,0.52, body extent -0.55,-0.3 0.55,0.3, height 0.6
0402L [mm] "0402 from SM-752 data"
  rect 0.6x0.5 smd: 1(-0.5,0) 2(0.5,0)
  body extent -0.55,-0.3 0.55,0.3, height 0.6
0603 [mm] "0603 from SM-752 data"
  rect 1x0.95 smd: 1(-0.8,0) 2(0.8,0)
  silkscreen extent -1.52,-0.69 1.52,0.69, body extent -0.87,-0.47 0.87,0.47, height 1
0603L [mm] "0603 from SM-752 data"
  rect 0.8x0.85 smd: 1(-0.7,0) 2(0.7,0)
  silkscreen extent -0.07,-0.33 0.07,0.33, body extent -0.87,-0.47 0.87,0.47, height 1
0805_HV [mil] "0805 with 30mil clearance between pads"
  rect 50x63 smd: 1(-40,0) 2(40,0)
  silkscreen extent -74,-40 74,40, body extent -43,-29 43,29, height 57
1206 [mm] "1206 from SM-752 data"
  rect 1.3x1.85 smd: 1(-1.45,0) 2(1.45,0)
  silkscreen extent -2.4,-1.21 2.4,1.21, body extent -1.7,-0.9 1.7,0.9, height 1.35
1210_280 [mm] "SMD, 2-Leads, Body 3.6x2.8mm, Height 2.8mm"
  rect 1.1x2.2 smd: 1(-1.65,0) 2(1.65,0)
  silkscreen extent -0.84,-1.4 0.84,1.4, body extent -1.8,-1.4 1.8,1.4, height 2.8
AssemblyNote [mil] "Assembly Note"
AssemblyNoteLabel [mil] "Assembly Note for PCB Labels"
DGN0008D_N [mm] "TSOP, 8-Leads, Body 3x3mm, Pitch 0.65mm, Thermal Pad 1.89x1.57mm, IPC Medium Density"
  rrect100% 1.35x0.45 smd: 1(-2.225,0.975) 2(-2.225,0.325) 3(-2.225,-0.325) 4(-2.225,-0.975) 5(2.225,-0.975) 6(2.225,-0.325) 7(2.225,0.325) 8(2.225,0.975)
  rrect6% 1.57x1.89 smd: 9(0,0)
  silkscreen extent -2.73,-1.55 0.95,1.55, body extent -2.46,-1.5 2.46,1.5, height 1.1
DRB0008F [mm] "SON, 8-Leads, Body 3x3mm, Pitch 0.65mm, Thermal Pad 2.4x1.6mm, TI Recommended"
  rrect33% 0.6x0.3 smd: 1(-1.4,0.975) 2(-1.4,0.325) 3(-1.4,-0.325) 4(-1.4,-0.975) 5(1.4,-0.975) 6(1.4,-0.325) 7(1.4,0.325) 8(1.4,0.975)
  rrect9% 1.47x1.07 on Top Paste: 9(0,-0.635) 9(0,0.635)
  rrect6% 1.6x2.4 smd paste-1.2: 9(0,0)
  silkscreen extent -1.73,-1.73 1.73,1.73, body extent -1.5,-1.5 1.5,1.5, height 0.77
EPSON_TSX-3225 [mm] "SMD, 4-Leads, Body 2.65x3.35mm, Height 0.6mm"
  rect 1.15x1.4 smd: 1(-0.8,1.1) 2(-0.8,-1.1) 3(0.8,-1.1) 4(0.8,1.1)
  silkscreen extent -1.33,-0.05 1.33,2.41, body extent -1.33,-1.68 1.33,1.68, height 0.61
FCC_disclaimer [mil]
Fiducial10-20#1 [mm]
  round 1 smd mask+0.5: 1(0,0)
  Top Layer keep-out circle w1.178: c0,0 r0.5
Fiducial10-20#2 [mm]
  round 1 smd mask+0.5: 1(-0.01,0)
  Top Layer keep-out circle w1.178: c0,0 r0.5
IND_LQG15H [mm] "MuRata"
  rect 0.55x0.6 smd: 1(-0.475,0) 2(0.475,0)
  silkscreen extent -1.3,-0.3 -0.95,0.3, body extent -0.52,-0.27 0.52,0.27, height 0.55
Kyocera_ST3215SB [mm] "SMD, 2-Leads, Body 3.2x1.5mm"
  rrect10% 1x1.55 smd: 1(-1.3,0) 2(1.3,0)
  body extent -1.65,-0.8 1.65,0.8, height 0.9
Label_650x200 [mil] "Thermal Transfer Label"
  round 1 on Mech14: 0(0,0)
  silkscreen extent -325,-100 325,100, body extent -325,-100 325,100, height 1
LED_SMLP12_BLUE [mm] "Rohm Semiconductor"
  rect 0.5x0.6 smd mask+0.08: 1(-0.45,0) 2(0.45,0)
  silkscreen extent 0.92,-0.3 0.92,0.3, body extent -0.55,-0.35 0.55,0.35, height 0.25
LED_SMLP12_ORANGE [mm] "Rohm Semiconductor"
  rect 0.5x0.6 smd mask+0.08: 1(-0.45,0) 2(0.45,0)
  silkscreen extent 0.92,-0.3 0.92,0.3, body extent -0.55,-0.35 0.55,0.35, height 0.25
LED_SMLP12_YELLOW [mm] "Rohm Semiconductor"
  rect 0.5x0.6 smd mask+0.08: 1(-0.45,0) 2(0.45,0)
  silkscreen extent 0.92,-0.3 0.92,0.3, body extent -0.55,-0.35 0.55,0.35, height 0.25
Pb-Free_Overlay_Small [mil]
  silkscreen extent -46,-46 46,46
Phoenix_1770898 [mm] "Terminal Block, 3 Pos, 2.5mm, R/A, TH"
  rrect50% 1.8x1.8 hole 1.2: 1(-2.5,-2.5) 1(-2.5,2.5)
  round 1.8 hole 1.2: 2(0,-2.5) 2(0,2.5) 3(2.5,-2.5) 3(2.5,2.5)
  body extent -3.1,-4.7 5,5.3, height 5
RGZ0048N [mm] "QFN, 48-Leads, Body 7x7mm, Pitch 0.5mm, Thermal Pad 5.15X5.15mm, TI recommended"
  rrect40% 0.6x0.25 smd: 1(-3.4,2.75) 2(-3.4,2.25) 3(-3.4,1.75) 4(-3.4,1.25) 5(-3.4,0.75) 6(-3.4,0.25) 7(-3.4,-0.25) 8(-3.4,-0.75) 9(-3.4,-1.25) 10(-3.4,-1.75) 11(-3.4,-2.25) 12(-3.4,-2.75) 25(3.4,-2.75) 26(3.4,-2.25) 27(3.4,-1.75) 28(3.4,-1.25) 29(3.4,-0.75) 30(3.4,-0.25) 31(3.4,0.25) 32(3.4,0.75) 33(3.4,1.25) 34(3.4,1.75) 35(3.4,2.25) 36(3.4,2.75)
  rrect40% 0.25x0.6 smd: 13(-2.75,-3.4) 14(-2.25,-3.4) 15(-1.75,-3.4) 16(-1.25,-3.4) 17(-0.75,-3.4) 18(-0.25,-3.4) 19(0.25,-3.4) 20(0.75,-3.4) 21(1.25,-3.4) 22(1.75,-3.4) 23(2.25,-3.4) 24(2.75,-3.4) 37(2.75,3.4) 38(2.25,3.4) 39(1.75,3.4) 40(1.25,3.4) 41(0.75,3.4) 42(0.25,3.4) 43(-0.25,3.4) 44(-0.75,3.4) 45(-1.25,3.4) 46(-1.75,3.4) 47(-2.25,3.4) 48(-2.75,3.4)
  rrect9% 1.06x1.06 on Top Paste: 49(-1.89,1.89) 49(-1.89,-0.63) 49(-1.89,0.63) 49(-1.89,-1.89) 49(-0.63,1.89) 49(-0.63,0.63) 49(-0.63,-0.63) 49(-0.63,-1.89) 49(0.63,1.89) 49(0.63,0.63) 49(0.63,-0.63) 49(0.63,-1.89) 49(1.89,1.89) 49(1.89,-0.63) 49(1.89,0.63) 49(1.89,-1.89)
  rrect2% 5.15x5.15 smd paste-2.6: 49(0,0)
  silkscreen extent -3.72,-3.72 3.72,3.72, body extent -3.5,-3.5 3.5,3.5, height 1
Samtec_FTSH-105-01-x-DV-K [mm] "Header(Shrouded), 1.27mm, 5x2, SMT"
  rect 2.79x0.74 smd: 1(-2.035,2.54) 2(2.035,2.54) 3(-2.035,1.27) 4(2.035,1.27) 5(-2.035,0) 6(2.035,0) 7(-2.035,-1.27) 8(2.035,-1.27) 9(-2.035,-2.54) 10(2.035,-2.54)
  silkscreen extent -3.73,-3.48 3.73,3.48, body extent -2.92,-3.18 2.92,3.17, height 6.13
SMB-Bi [mil] "Molded Diode, 2-Leads, Body 5.4x3.6mm, IPC Medium Density, based on OnSemi component dimensions"
  rect 85x107.99 smd: 1(-87.01,0) 2(87.01,0)
  silkscreen extent -125,-79 125,79, body extent -104,-73 104,73, height 89
SML-P1_GREEN [mm] "ROHM"
  rect 0.5x0.6 smd: 1(-0.45,0) 2(0.45,0)
  silkscreen extent -0.95,-0.3 -0.95,0.3, body extent -0.53,-0.33 0.53,0.33, height 0.25
SML-P1_RED [mm] "ROHM"
  rect 0.5x0.6 smd: 1(-0.45,0) 2(0.45,0)
  silkscreen extent -0.95,-0.3 -0.95,0.3, body extent -0.52,-0.33 0.52,0.33, height 0.25
SOD-123 [mm] "On Semi recommended land pattern"
  rect 0.915x1.22 smd: 1(-1.637,0) 2(1.637,0)
  silkscreen extent -2.74,-1.17 2.03,1.17, body extent -1.93,-0.9 1.93,0.9, height 1.35
SOD-323 [mm] "NXP recommended land pattern"
  rect 0.6x0.6 smd paste-0.05: 1(-1.1,0) 2(1.1,0)
  silkscreen extent -2.06,-0.86 1.53,0.86, body extent -1.3,-0.67 1.3,0.68, height 1.1
SOT-363 [mm]
  rect 0.6x0.42 smd mask+0.051: 1(-0.95,0.65) 2(-0.95,0) 3(-0.95,-0.65) 4(0.95,-0.65) 5(0.95,0) 6(0.95,0.65)
  silkscreen extent -0.38,-1.02 0.38,1.02, body extent -1.1,-1.1 1.1,1.1, height 1.12
Sullins_PEC06SAAN [mm] "TH, 6-Leads, Body 608x100mil, Pitch 100mil"
  rect 1.5x1.5 hole 1.016: 1(-6.35,0)
  round 1.5 hole 1.016: 2(-3.81,0) 3(-1.27,0) 4(1.27,0) 5(3.81,0) 6(6.35,0)
  silkscreen extent -8.64,-1.27 7.72,1.27, body extent -7.72,-1.27 7.72,1.27, height 8.59
SW_B3U-1100P [mm] "SMD, 3-Leads, Body 3x2.5mm"
  rect 0.8x1.8 smd: 1(-1.7,0) 2(1.7,0)
  rect 0.8x1.2 smd: 3(0,1.65)
  silkscreen extent -2.16,-1.25 1.5,1.9, body extent -2,-1.25 2,1.9, height 1.6

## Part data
C1: library part CMP-0007134-5, "CAP, CERM, 2.2 uF, 6.3 V, +/- 10%, X7R, AEC-Q200 Grade 1, 0603", Cap_Case=0603, Manufacturer=MuRata, Supplier Part Number 1=490-5316-1-ND, TempCo=X7R, Tolerance_%=10%, Value1=Unknown, Value2=6.3V, ValueDisplayed=2.2uF
C2: library part CMP-0079095-1, "CAP, CERM, 0.1 µF, 50 V,+/- 10%, X7R, AEC-Q200 Grade 1, 0603", Cap_Case=0603, Manufacturer=AVX, Supplier Part Number 1=478-3540-1-ND, TempCo=X7R, Tolerance_%=10%, Value2=50V, ValueDisplayed=0.1µF
C3: library part CMP-0009258-2, "CAP, CERM, 10 uF, 50 V, +/- 10%, X7R, AEC-Q200 Grade 1, 1210", Cap_Case=1210, Manufacturer="Taiyo Yuden", Supplier Part Number 1=587-4326-1-ND, TempCo=X7R, Tolerance_%=10%, Value1=Unknown, Value2=50V, ValueDisplayed=10uF
C4 C6: library part CMP-0006356-2, "CAP, CERM, 0.1 uF, 50 V, +/- 10%, X7R, AEC-Q200 Grade 1, 0402", Cap_Case=0402, Manufacturer=MuRata, Supplier Part Number 1=490-10672-1-ND, TempCo=X7R, Tolerance_%=10%, Value1=Unknown, Value2=50V, ValueDisplayed=0.1uF
C5: library part CMP-0006703-2, "CAP, CERM, 220 pF, 100 V, +/- 10%, X7R, 0402", Cap_Case=0402, Manufacturer=MuRata, Supplier Part Number 1=GRM155R72A221KA01D-ND, TempCo=X7R, Tolerance_%=10%, Value1=Unknown, Value2=100V, ValueDisplayed=220pF
C7 C8 C9 C10 C12 C13 C26: library part CMP-0006343-2, "CAP, CERM, 0.1 uF, 10 V, +/- 10%, X7R, 0402", Cap_Case=0402, Manufacturer="Samsung Electro-Mechanics", TempCo=X7R, Tolerance_%=10%, Value1=Unknown, Value2=10V, ValueDisplayed=0.1uF
C11 C14: library part CMP-0007497-5, "CAP, CERM, 10 uF, 10 V, +/- 20%, X7R, 0603", Cap_Case=0603, Manufacturer=MuRata, Supplier Part Number 1=81-GRM188Z71A106MA3D, TempCo=X7R, Tolerance_%=20%, Value1=Unknown, Value2=10V, ValueDisplayed=10uF
C15 C16 C18 C19 C21: library part CMP-0006415-2, "CAP, CERM, 12 pF, 50 V, +/- 5%, C0G/NP0, 0402", Cap_Case=0402, Manufacturer=MuRata, Supplier Part Number 1=14T3292, TempCo=C0G/NP0, Tolerance_%=5%, Value1=Unknown, Value2=50V, ValueDisplayed=12pF
C17: library part CMP-0006488-2, "CAP, CERM, 6.8 pF, 50 V, +/- 5%, C0G/NP0, 0402", Cap_Case=0402, Manufacturer=MuRata, Supplier Part Number 1=81-GRM1555C1H6R8CA1D, TempCo=C0G/NP0, Tolerance_%=5%, Value1=Unknown, Value2=50V, ValueDisplayed=6.8pF
C20 C22 C23 C25: library part CMP-0006427-2, "CAP, CERM, 1 pF, 50 V, +/- 5%, C0G/NP0, 0402", Cap_Case=0402, Manufacturer=MuRata, Supplier Part Number 1=490-3199-1-ND, TempCo=C0G/NP0, Tolerance_%=5%, Value1=Unknown, Value2=50V, ValueDisplayed=1pF
C24: library part CMP-0007365-4, "CAP, CERM, 1 uF, 10 V, +/- 10%, X7R, 0603", Cap_Case=0603, Manufacturer=MuRata, Supplier Part Number 1=490-3899-1-ND, TempCo=X7R, Tolerance_%=10%, Value1="0.011 ohm", Value2=10V, ValueDisplayed=1uF
D1: library part CMP-0029150-1, "Diode, Switching, 200 V, 0.2 A, AEC-Q101, SOD-323", Manufacturer="ON Semiconductor", Supplier Part Number 1=BAS20HT1GOSCT-ND, Value1=0.2A, Value2=1.25V
D2: library part CMP-0076974-1, "Diode, Switching, 100 V, 0.15 A, SOD-123", Manufacturer="Micro Commercial Components", Supplier Part Number 1=1N4148WTPMSCT-ND, Value1=0.15A, Value2=1.25V
D3: library part CMP-0006050-2, "Diode, TVS, Bi, 39 V, SMB", Manufacturer=STMicroelectronics, Supplier Part Number 1=497-6498-1-ND, Value1=W
D4: library part CMP-0002873-1, "LED, Green, SMD", Color=green, Manufacturer=Rohm, Supplier Part Number 1=511-1592-1-ND, Value1=W, Value2=2.2V
D5: library part CMP-0002838-1, "LED, Blue, SMD", Color=blue, Manufacturer=Rohm, Supplier Part Number 1=511-1615-1-ND, Value1=W, Value2=2.9V
D6: library part CMP-0002839-1, "LED, Yellow, SMD", Color=yellow, Manufacturer=Rohm, Supplier Part Number 1=511-1595-1-ND, Value1=W, Value2=2.1V
D7: library part CMP-0002841-1, "LED, Orange, SMD", Color=orange, Manufacturer=Rohm, Supplier Part Number 1=511-1590-1-ND, Value1=W, Value2=2.1V
D8: library part CMP-0003003-2, "LED, Red, SMD", Color=Red, Manufacturer=Rohm, Power_TotalModule=50mW, Supplier Part Number 1=511-1594-1-ND, Value1=0.05W, Value2=2V
FID1 FID2 FID3 FID4 FID5 FID6: library part CMP-0077181-1, "Fiducial mark.  There is nothing to buy or mount.", Manufacturer=N/A
J1: library part CMP-0084507-1, "Terminal Block, 3 Pos, 2.5mm, R/A, TH", Color=Black, Current_A=6A, Manufacturer="Phoenix Contact", Voltage_V=160V
J2: library part CMP-0054567-1, "Header, 100mil, 6x1, Tin, TH", Manufacturer="Sullins Connector Solutions", Supplier Part Number 1=S1012E-06-ND
J3: library part CMP-0075670-2, "Header (Shrouded), 1.27mm, 5x2, Gold, SMT", Color=Black, Current_A=3.3A, Manufacturer=Samtec, Supplier Part Number 1=SAM8796-ND
L1: library part CMP-0003349-2, "Ferrite Bead, 1500 ohm @ 100 MHz, 0.5 A, 0603", Manufacturer=MuRata, Supplier Part Number 1=490-5216-1-ND, Value1="0.5 ohm", Value2=0.5A, ValueDisplayed="1500 ohm"
L2: library part CMP-0059606-1, "Inductor, Multilayer, Ferrite, 10 uH, 0.11 A, 0.52 ohm, SMD", Manufacturer="Taiyo Yuden", Supplier Part Number 1=587-2608-1-ND, Value1="0.52 ohm", Value2=0.11A, ValueDisplayed=10uH
L3 L6: library part CMP-0058626-1, "Inductor, Multilayer, Air Core, 2.4 nH, 0.3 A, 0.15 ohm, SMD", Manufacturer=MuRata, Supplier Part Number 1=LQG15HS2N4S02D-ND, Value1="0.15 ohm", Value2=0.3A, ValueDisplayed=2.4nH
L4 L5: library part CMP-0058624-1, "Inductor, Multilayer, Air Core, 2 nH, 0.3 A, 0.1 ohm, SMD", Manufacturer=MuRata, Supplier Part Number 1=490-6569-1-ND, Value1="0.1 ohm", Value2=0.3A, ValueDisplayed=2nH
LBL1: library part CMP-0003625-1, "Thermal Transfer Printable Labels, 0.650\" W x 0.200\" H - 10,000 per roll", Manufacturer=Brady, Supplier Part Number 1=97C5133
Logo2: library part CMP-0074839-1
Logo3: library part CMP-0074847-1, "FCC_disclaimer"
R1: library part CMP-0026822-3, "RES, 0, 5%, 0.063 W, AEC-Q200 Grade 0, 0402", Manufacturer=Vishay-Dale, Power_W=63mW, Supplier Part Number 1=541-0.0JCT-ND, TempCo="200 ppm/C", Tolerance_%=5%, Value2=0.063W, Value_Code=0000, ValueDisplayed=0
R2: library part CMP-0026825-5, "RES, 10 k, 5%, 0.063 W, AEC-Q200 Grade 0, 0402", Manufacturer=Vishay-Dale, Power_W=63mW, Supplier Part Number 1=541-10KJCT-ND, TempCo="200 ppm/C", Tolerance_%=5%, Value2=0.063W, Value_Code=10k0, ValueDisplayed=10k
R3 R4: library part CMP-0018158-2, "RES, 2.00 k, 1%, 0.25 W, 1206", Manufacturer="Yageo America", Power_W=250mW, Supplier Part Number 1=311-2.00KFRCT-ND, TempCo="100 ppm/C", Tolerance_%=1%, Value2=0.25W, Value_Code=2k00, ValueDisplayed=2.00k
R5 R13: library part CMP-0026995-2, "RES, 100 k, 5%, 0.1 W, AEC-Q200 Grade 0, 0402", Manufacturer=Panasonic, Power_W=100mW, Supplier Part Number 1=P100KJCT-ND, TempCo="200 ppm/C", Tolerance_%=5%, Value2=0.1W, Value_Code=100k
R6 R7: library part CMP-0025729-4, "RES, 1.0 k, 5%, 0.1 W, AEC-Q200 Grade 0, 0603", Manufacturer=Vishay-Dale, Power_W=100mW, Supplier Part Number 1=541-1.0KGCT-ND, TempCo="200 ppm/C", Tolerance_%=5%, Value2=0.1W, Value_Code=1k00, ValueDisplayed=1.0k
R8: library part CMP-0026878-3, "RES, 220, 5%, 0.063 W, AEC-Q200 Grade 0, 0402", Manufacturer=Vishay-Dale, Power_W=63mW, Supplier Part Number 1=541-220JCT-ND, TempCo="200 ppm/C", Tolerance_%=5%, Value2=0.063W, Value_Code=220R, ValueDisplayed=220
R9: library part CMP-0026837-3, "RES, 130, 5%, 0.063 W, AEC-Q200 Grade 0, 0402", Manufacturer=Vishay-Dale, Power_W=63mW, Supplier Part Number 1=541-130JCT-ND, TempCo="200 ppm/C", Tolerance_%=5%, Value2=0.063W, Value_Code=130R, ValueDisplayed=130
R10 R11: library part CMP-0026934-3, "RES, 470, 5%, 0.063 W, AEC-Q200 Grade 0, 0402", Manufacturer=Vishay-Dale, Power_W=63mW, Supplier Part Number 1=541-470JCT-ND, TempCo="200 ppm/C", Tolerance_%=5%, Value2=0.063W, Value_Code=470R, ValueDisplayed=470
R12: library part CMP-0026930-3, "RES, 430, 5%, 0.063 W, AEC-Q200 Grade 0, 0402", Manufacturer=Vishay-Dale, Power_W=63mW, Supplier Part Number 1=541-430JCT-ND, TempCo="200 ppm/C", Tolerance_%=5%, Value2=0.063W, Value_Code=430R, ValueDisplayed=430
S1: library part CMP-0002193-2, "Switch, SPST-NO, Off-Mom, 12 V, SMD", CurrentRating_mA=50A, Manufacturer="Omron Electronic Components", Supplier Part Number 1=SW1021CT-ND
U1: library part CMP-0013312-4, "300mA High-Voltage Ultra-Low-Iq Low-Dropout (LDO) Regulator, DGN0008D (VSSOP-8)", Alternate Manufacturer="Texas Instruments"
U2: library part CMP-0079115-1, "Local Interconnect Network (LIN) Transceiver with Dominant State Timeout, DRB0008F (VSON-8)", Alternate Manufacturer="Texas Instruments", Alternate PartNumber=TLIN1029DRBTQ1
U3: library part CMP-0079117-1, "Automotive Qualified SimpleLink Bluetooth low energy Wireless MCU, RGZ0048N (VQFN-48)", Alternate Manufacturer="Texas Instruments", Alternate PartNumber=CC2640R2FTWRGZTQ1
U4: library part CMP-0084444-1, "20 MHz to 3.0 GHz SPDT Switch, SOT-363", Manufacturer="Skyworks Solutions"
Y1: library part CMP-0004609-3, "Crystal, 24 MHz, 9 pF, SMD", Frequency_Fixed=24MHz, Frequency Stability=+/-20ppm, Manufacturer=Epson, Supplier Part Number 1=SER3634CT-ND
Y2: library part CMP-0079334-1, "Crystal, 32.768 KHz, 20 ppm, SMD", Frequency_Fixed=32.768kHz, Frequency Tolerance="20 ppm", Manufacturer=Kyocera, Supplier Part Number 1=1253-1403-1-ND
ZZ1: library part CMP-0003616-3
ZZ2: library part CMP-0077236-1
ZZ3: library part CMP-0077237-1
ZZ4: library part CMP-0077238-1

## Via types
v1: diameter 19.68, hole 7.87, Top Layer to Bottom Layer, tented both sides, 192 vias
v2: diameter 19.68, hole 7.87, Top Layer to Bottom Layer, 63 vias
v3: diameter 34, hole 16, Top Layer to Bottom Layer, tented both sides, 4 vias
v4: diameter 19.68/19.68/19.68/19.68/19.68/19.68 (per signal layer), hole 7.87, Top Layer to Bottom Layer, tented both sides, 1 vias

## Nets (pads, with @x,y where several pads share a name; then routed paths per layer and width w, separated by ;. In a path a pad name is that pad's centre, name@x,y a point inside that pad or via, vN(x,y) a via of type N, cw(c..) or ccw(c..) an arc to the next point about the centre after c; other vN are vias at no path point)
ANT_SEL1: R7.1 U3.42 | length 663.6
  Top Layer w7: v1(739.41,1288.38) 729.41,1298.38 729.41,1353.38 738.41,1362.38 758.21,1362.38 763.21,1367.38 763.41,1367.38 818.57,1422.53 U3.42@818.57,1441.52 ; v1(1047.41,1277.38) R7.1@1192.48,1277.38
  Bottom Layer w7: v1(739.41,1288.38) 750.41,1277.38 v1(1047.41,1277.38)
ANT_SEL2: R6.1 U3.6 | length 588.9
  Top Layer w10: U3.6@962.27,1565.53 1001.52,1565.53 1107.41,1671.42 1107.41,1733.38 1122.3,1748.27 1270.52,1748.27 1328.58,1690.2 1363.58,1690.2 1378.58,1675.2 R6.1@1378.58,1644.87
Antenna1: U4.1 | length 749.7
  Top Layer w5.91: v3(1435,1178) 1473.41,1216.41 U4.1@1473.41,1219.6
  Layer4 w7.87: 811,1070 811,1110 835,1134 1003,1134 1022,1153 1410,1153 v3(1435,1178)
Antenna2: U4.3 | length 751.5
  Top Layer w5.91: U4.3@1524.59,1219.6 1524.59,1216.41 v3(1563,1178)
  Layer4 w7.87: v3(1563,1178) 1588,1153 2144,1153 2189,1108 2189,1069
Balun_Out: C21.1 U4.5 | length 79.9
  Top Layer w6.75: U4.5@1499,1294.4 C21.1@1499,1374.25
DCOUPL: C24.1 U3.23 | length 73.2
  Top Layer w10: C24.1@718.03,1773.38 718.03,1749.75 739.83,1727.96 U3.23@739.83,1709.23
DIO_5: J2.6 U3.10 | length 1060.8
  Top Layer w10: U3.10@962.27,1644.27 984.1,1644.27 1028.41,1688.58 1028.41,1735.35 v1(1028.53,1735.47)
  Bottom Layer w10: v1(1028.53,1735.47) 1047.23,1754.17 1202.74,1754.17 1254.91,1702 1812.97,1702 J2.6@1894.67,1783.7
DIO_6: J2.5 U3.11 | length 964.2
  Top Layer w10: U3.11@962.27,1663.96 979.74,1663.96 991.13,1675.34 v1(991.13,1735.47)
  Bottom Layer w10: v1(991.13,1735.47) 1035.42,1779.76 1214.55,1779.76 1271.31,1723 1733.97,1723 J2.5@1794.67,1783.7
EN: R1.2 U1.2 | length 158.9
  Top Layer w10: R1.2@1827.82,1508.51 1827.82,1541.78 1839.41,1553.38 1869.41,1553.38 1879.41,1563.38 1879.41,1583.38 1892.61,1596.58 U1.2@1919.01,1596.58
EN_LIN: R5.2 U2.2 U3.9 | length 1693.5
  Top Layer w10: U3.9@962.27,1624.59 988.45,1624.59 1056.41,1692.54 1056.41,1763.38 1110.73,1817.7 1316.19,1817.7 1335.49,1837 1508.69,1837 1541.32,1804.37 1541.32,1749.32 1459.41,1667.41 1459.41,1622.42 1509.43,1572.4 1526.39,1572.4 1565.41,1533.38 1614.41,1533.38 1863.2,1284.59 1961.77,1284.59 1982.89,1305.71 R5.2@1982.89,1327.59 2007.27,1327.59 2020.06,1340.38 U2.2@2039.15,1340.38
